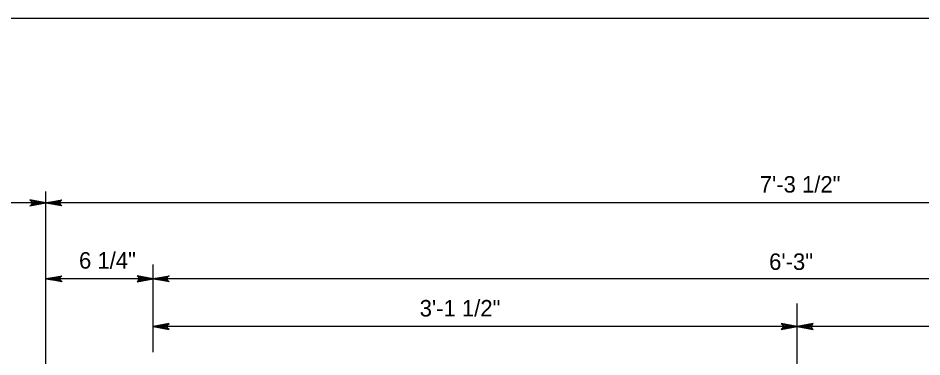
# Model space of a CAD drawing. Extents: x 632007860 to 635435983, y 295418622 to 297794622.
# Drawn here: x 632975056 to 633141977, y 297123007 to 297185622 of the extents above; entities that cross this region are included whole.
import ezdxf

# ---------------------------------------------------------------- set-up
doc = ezdxf.new("R2010")
doc.units = 0
for name, color, linetype in [('1', 7, 'Continuous'), ('8', 7, 'Continuous'), ('S-DETL-DIMS', 7, 'Continuous'), ('S-DETL-T120', 7, 'Continuous')]:
    doc.layers.add(name, color=color, linetype=linetype)

msp = doc.modelspace()

# ---------------------------------------------------------------- linework, layer by layer
at = {"layer": '1'}
msp.add_line((632888860, 297185622), (633674860, 297185622), dxfattribs=at)
at = {"layer": '8'}
msp.add_line((633118962, 297041711), (633118962, 297132869), dxfattribs=at)
at = {"layer": 'S-DETL-DIMS'}
for p, q in [((632980202, 297108021), (632980202, 297153588)), ((632980202, 297151471), (632929466, 297151471)), ((633257266, 297151471), (632980202, 297151471)), ((632999992, 297123866), (632999992, 297140088)), ((633257266, 297137465), (632980202, 297137465)), ((633118962, 297099227), (633118962, 297132869)), ((633118962, 297128629), (632999992, 297128629)), ((633237476, 297128629), (633118962, 297128629))]:
    msp.add_line(p, q, dxfattribs=at)
for points in [[(632980202, 297151471), (632977242, 297152026), (632977470, 297151868), (632977588, 297151670), (632977622, 297151471), (632977588, 297151273), (632977470, 297151074), (632977242, 297150916), (632980202, 297151471), (632977470, 297151074), (632977588, 297151273), (632980202, 297151471), (632977622, 297151471), (632977588, 297151670), (632980202, 297151471), (632977470, 297151868)], [(632980202, 297151471), (632983161, 297152026), (632983047, 297151947), (632982933, 297151868), (632982874, 297151769), (632982815, 297151670), (632982798, 297151570), (632982781, 297151471), (632982798, 297151372), (632982815, 297151273), (632982874, 297151174), (632982933, 297151074), (632983047, 297150995), (632983161, 297150916), (632980202, 297151471), (632983047, 297150995), (632982933, 297151074), (632980202, 297151471), (632982874, 297151174), (632982815, 297151273), (632980202, 297151471), (632982798, 297151372), (632982781, 297151471), (632980202, 297151471), (632982798, 297151570), (632982815, 297151670), (632980202, 297151471), (632982874, 297151769), (632982933, 297151868), (632980202, 297151471), (632983047, 297151947)], [(632980202, 297137465), (632983161, 297138020), (632983047, 297137941), (632982933, 297137862), (632982874, 297137763), (632982815, 297137664), (632982798, 297137564), (632982781, 297137465), (632982798, 297137366), (632982815, 297137267), (632982874, 297137167), (632982933, 297137068), (632983047, 297136989), (632983161, 297136910), (632980202, 297137465), (632983047, 297136989), (632982933, 297137068), (632980202, 297137465), (632982874, 297137167), (632982815, 297137267), (632980202, 297137465), (632982798, 297137366), (632982781, 297137465), (632980202, 297137465), (632982798, 297137564), (632982815, 297137664), (632980202, 297137465), (632982874, 297137763), (632982933, 297137862), (632980202, 297137465), (632983047, 297137941)], [(632999992, 297137465), (632997033, 297138020), (632997261, 297137862), (632997378, 297137664), (632997412, 297137465), (632997378, 297137267), (632997261, 297137068), (632997033, 297136910), (632999992, 297137465), (632997261, 297137068), (632997378, 297137267), (632999992, 297137465), (632997412, 297137465), (632997378, 297137664), (632999992, 297137465), (632997261, 297137862)], [(632999992, 297137465), (633002951, 297138020), (633002837, 297137941), (633002723, 297137862), (633002664, 297137763), (633002606, 297137664), (633002589, 297137564), (633002572, 297137465), (633002589, 297137366), (633002606, 297137267), (633002664, 297137167), (633002723, 297137068), (633002837, 297136989), (633002951, 297136910), (632999992, 297137465), (633002837, 297136989), (633002723, 297137068), (632999992, 297137465), (633002664, 297137167), (633002606, 297137267), (632999992, 297137465), (633002589, 297137366), (633002572, 297137465), (632999992, 297137465), (633002589, 297137564), (633002606, 297137664), (632999992, 297137465), (633002664, 297137763), (633002723, 297137862), (632999992, 297137465), (633002837, 297137941)], [(632999992, 297128629), (633002951, 297128074), (633002723, 297128232), (633002606, 297128431), (633002572, 297128629), (633002606, 297128827), (633002723, 297129026), (633002951, 297129184), (632999992, 297128629), (633002723, 297129026), (633002606, 297128827), (632999992, 297128629), (633002572, 297128629), (633002606, 297128431), (632999992, 297128629), (633002723, 297128232)], [(633118962, 297128629), (633116003, 297129184), (633116231, 297129026), (633116348, 297128827), (633116382, 297128629), (633116348, 297128431), (633116231, 297128232), (633116003, 297128074), (633118962, 297128629), (633116231, 297128232), (633116348, 297128431), (633118962, 297128629), (633116382, 297128629), (633116348, 297128827), (633118962, 297128629), (633116231, 297129026)], [(633118962, 297128629), (633121921, 297128074), (633121693, 297128232), (633121576, 297128431), (633121542, 297128629), (633121576, 297128827), (633121693, 297129026), (633121921, 297129184), (633118962, 297128629), (633121693, 297129026), (633121576, 297128827), (633118962, 297128629), (633121542, 297128629), (633121576, 297128431), (633118962, 297128629), (633121693, 297128232)]]:
    msp.add_lwpolyline(points, dxfattribs=at)

# ---------------------------------------------------------------- texts
at = {"layer": 'S-DETL-T120'}
for s, p in [('7\'-3 1/2"', (633112026, 297153377)), ('6 1/4"', (632986307, 297139323)), ('6\'-3"', (633113757, 297139084)), ('3\'-1 1/2"', (633049221, 297130481))]:
    msp.add_text(s, height=3048, dxfattribs=at).set_placement(p)

doc.saveas('drawing.dxf')
